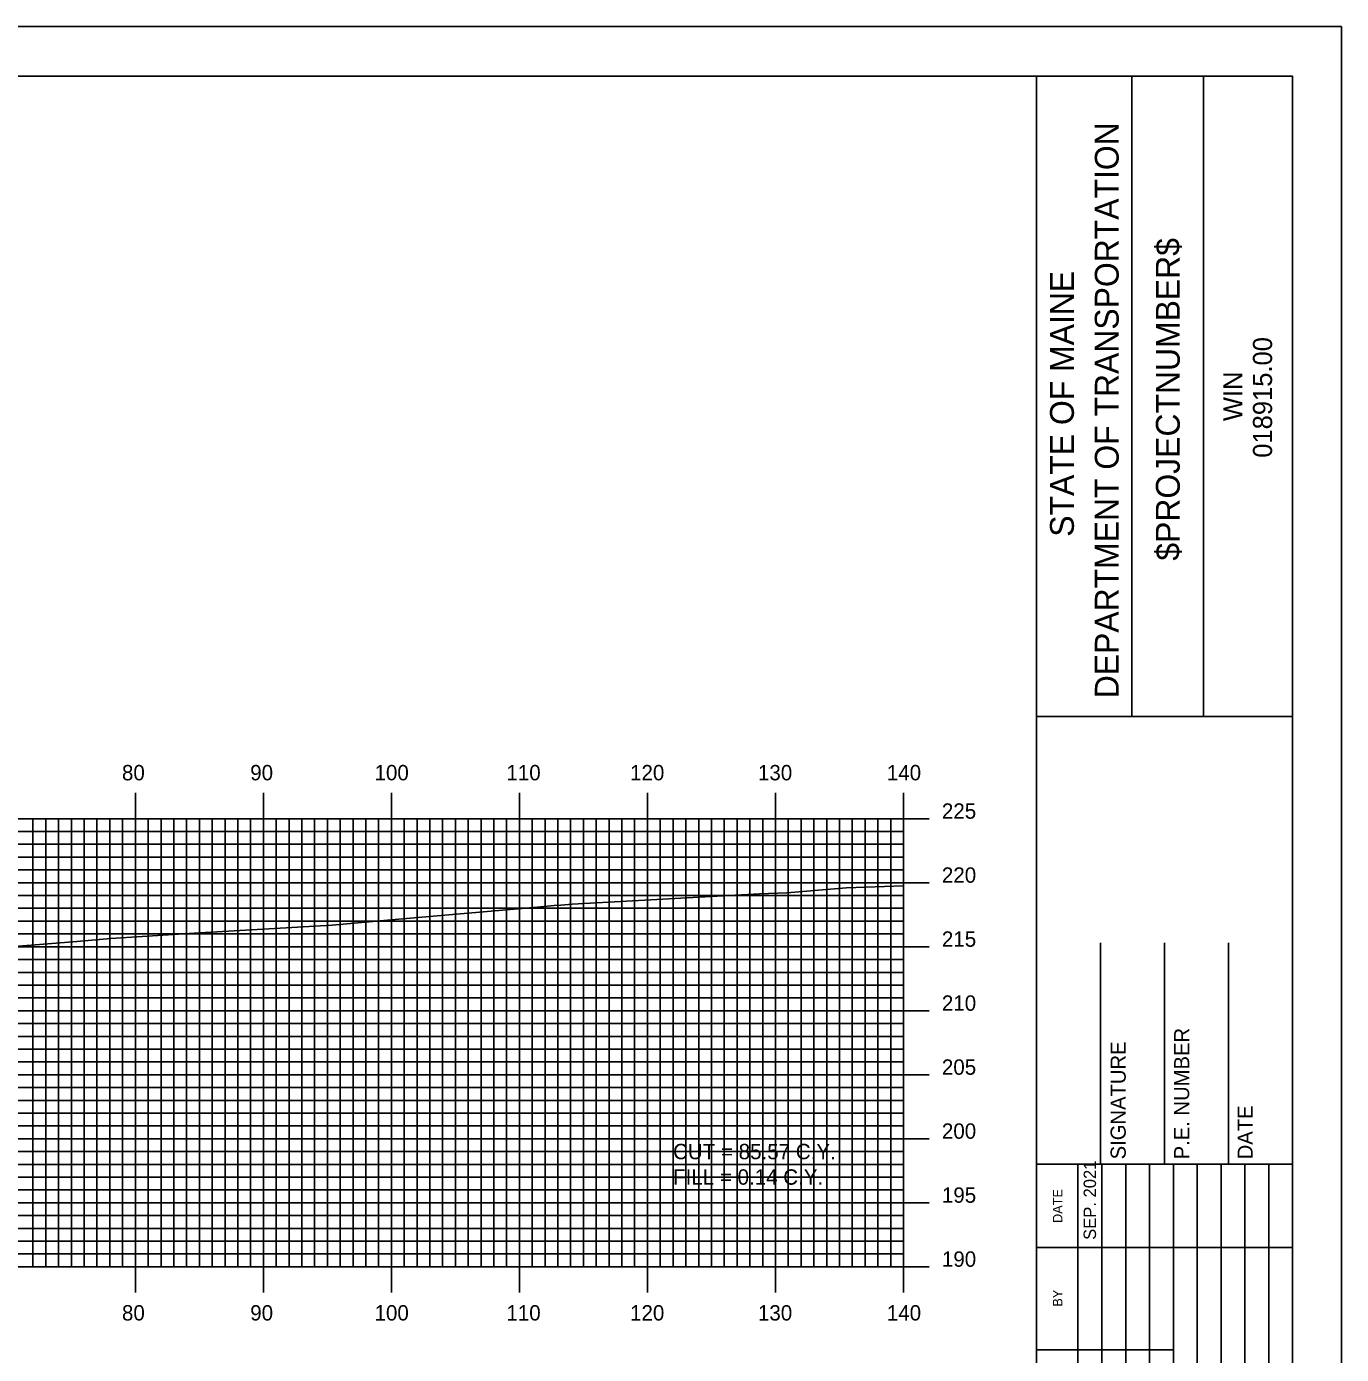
# Model space of a CAD drawing. Extents: x 852135 to 852479, y 364785 to 365005.
# Drawn here: x 852372.7 to 852475.4, y 364901.4 to 365005.1 of the extents above; entities that cross this region are included whole.
import ezdxf

# ---------------------------------------------------------------- set-up
doc = ezdxf.new("R2010")
doc.units = 0
for name, color, linetype in [('BORDER', 7, 'Continuous'), ('D_Text_Standard', 7, 'Continuous'), ('H_V ANNOTATION', 7, 'Continuous'), ('MAJOR', 7, 'Continuous'), ('MINOR', 7, 'Continuous'), ('PLOT BOUNDARY', 7, 'Continuous'), ('S_Roadway_Centerline', 7, 'Continuous')]:
    doc.layers.add(name, color=color, linetype=linetype)

msp = doc.modelspace()

# ---------------------------------------------------------------- linework, layer by layer
at = {"layer": 'BORDER'}
for p, q in [((852451.62, 364791.23), (852451.62, 365001.23)), ((852459.07, 364951.23), (852459.07, 365001.23)), ((852464.66, 364951.23), (852464.66, 365001.23)), ((852451.62, 364951.22), (852471.62, 364951.22)), ((852456.62, 364916.24), (852456.62, 364933.53)), ((852461.62, 364916.24), (852461.62, 364933.53)), ((852466.62, 364916.24), (852466.62, 364933.53)), ((852451.62, 364916.24), (852471.62, 364916.24))]:
    msp.add_line(p, q, dxfattribs=at)
msp.add_lwpolyline([(852151.62, 364791.23), (852471.62, 364791.23), (852471.62, 365001.23), (852151.62, 365001.23)], close=True, dxfattribs=at)
for points in [[(852454.85, 364909.74), (852454.85, 364916.24)], [(852456.71, 364881.24), (852456.71, 364916.24)], [(852458.58, 364916.24), (852458.58, 364881.24)], [(852460.44, 364881.24), (852460.44, 364916.24)], [(852462.3, 364881.24), (852462.3, 364916.24)], [(852464.17, 364881.24), (852464.17, 364916.24)], [(852466.03, 364881.24), (852466.03, 364916.24)], [(852467.89, 364881.24), (852467.89, 364916.24)], [(852469.76, 364881.24), (852469.76, 364916.24)], [(852454.85, 364881.24), (852454.85, 364914.83)], [(852451.62, 364909.74), (852471.62, 364909.74)], [(852451.62, 364901.74), (852454.85, 364901.74)], [(852454.85, 364901.74), (852462.3, 364901.74)]]:
    msp.add_lwpolyline(points, dxfattribs=at)
at = {"layer": 'MAJOR'}
for p, q in [((852381.22, 364945.24), (852381.22, 364943.23)), ((852391.22, 364945.24), (852391.22, 364943.23)), ((852401.22, 364945.24), (852401.22, 364943.23)), ((852411.22, 364945.24), (852411.22, 364943.23)), ((852421.22, 364945.24), (852421.22, 364943.23)), ((852431.22, 364945.24), (852431.22, 364943.23)), ((852441.22, 364945.24), (852441.22, 364943.23)), ((852161.22, 364943.23), (852441.22, 364943.23)), ((852161.22, 364943.23), (852441.22, 364943.23)), ((852381.22, 364908.23), (852381.22, 364943.23)), ((852391.22, 364908.23), (852391.22, 364943.23)), ((852401.22, 364908.23), (852401.22, 364943.23)), ((852411.22, 364908.23), (852411.22, 364943.23)), ((852421.22, 364908.23), (852421.22, 364943.23)), ((852431.22, 364908.23), (852431.22, 364943.23)), ((852443.22, 364943.23), (852439.21, 364943.23)), ((852441.22, 364908.23), (852441.22, 364943.23)), ((852441.22, 364908.23), (852441.22, 364943.23)), ((852161.22, 364938.23), (852441.22, 364938.23)), ((852443.22, 364938.23), (852439.21, 364938.23)), ((852161.22, 364933.23), (852441.22, 364933.23)), ((852443.22, 364933.23), (852439.21, 364933.23)), ((852161.22, 364928.23), (852441.22, 364928.23)), ((852443.22, 364928.23), (852439.21, 364928.23)), ((852161.22, 364923.23), (852441.22, 364923.23)), ((852443.22, 364923.23), (852439.21, 364923.23)), ((852161.22, 364918.23), (852441.22, 364918.23)), ((852443.22, 364918.23), (852439.21, 364918.23)), ((852161.22, 364913.23), (852441.22, 364913.23)), ((852443.22, 364913.23), (852439.21, 364913.23)), ((852161.22, 364908.23), (852441.22, 364908.23)), ((852161.22, 364908.23), (852441.22, 364908.23)), ((852381.22, 364906.23), (852381.22, 364908.23)), ((852391.22, 364906.23), (852391.22, 364908.23)), ((852401.22, 364906.23), (852401.22, 364908.23)), ((852411.22, 364906.23), (852411.22, 364908.23)), ((852421.22, 364906.23), (852421.22, 364908.23)), ((852431.22, 364906.23), (852431.22, 364908.23)), ((852443.22, 364908.23), (852439.21, 364908.23)), ((852441.22, 364906.23), (852441.22, 364908.23))]:
    msp.add_line(p, q, dxfattribs=at)
at = {"layer": 'MINOR'}
for p, q in [((852373.22, 364908.23), (852373.22, 364943.23)), ((852374.22, 364908.23), (852374.22, 364943.23)), ((852375.22, 364908.23), (852375.22, 364943.23)), ((852376.22, 364908.23), (852376.22, 364943.23)), ((852377.22, 364908.23), (852377.22, 364943.23)), ((852378.22, 364908.23), (852378.22, 364943.23)), ((852379.22, 364908.23), (852379.22, 364943.23)), ((852380.22, 364908.23), (852380.22, 364943.23)), ((852382.22, 364908.23), (852382.22, 364943.23)), ((852383.22, 364908.23), (852383.22, 364943.23)), ((852384.22, 364908.23), (852384.22, 364943.23)), ((852385.22, 364908.23), (852385.22, 364943.23)), ((852386.22, 364908.23), (852386.22, 364943.23)), ((852387.22, 364908.23), (852387.22, 364943.23)), ((852388.22, 364908.23), (852388.22, 364943.23)), ((852389.22, 364908.23), (852389.22, 364943.23)), ((852390.22, 364908.23), (852390.22, 364943.23)), ((852392.22, 364908.23), (852392.22, 364943.23)), ((852393.22, 364908.23), (852393.22, 364943.23)), ((852394.22, 364908.23), (852394.22, 364943.23)), ((852395.22, 364908.23), (852395.22, 364943.23)), ((852396.22, 364908.23), (852396.22, 364943.23)), ((852397.22, 364908.23), (852397.22, 364943.23)), ((852398.22, 364908.23), (852398.22, 364943.23)), ((852399.22, 364908.23), (852399.22, 364943.23)), ((852400.22, 364908.23), (852400.22, 364943.23)), ((852402.22, 364908.23), (852402.22, 364943.23)), ((852403.22, 364908.23), (852403.22, 364943.23)), ((852404.22, 364908.23), (852404.22, 364943.23)), ((852405.22, 364908.23), (852405.22, 364943.23)), ((852406.22, 364908.23), (852406.22, 364943.23)), ((852407.22, 364908.23), (852407.22, 364943.23)), ((852408.22, 364908.23), (852408.22, 364943.23)), ((852409.22, 364908.23), (852409.22, 364943.23)), ((852410.22, 364908.23), (852410.22, 364943.23)), ((852412.22, 364908.23), (852412.22, 364943.23)), ((852413.22, 364908.23), (852413.22, 364943.23)), ((852414.22, 364908.23), (852414.22, 364943.23)), ((852415.22, 364908.23), (852415.22, 364943.23)), ((852416.22, 364908.23), (852416.22, 364943.23)), ((852417.22, 364908.23), (852417.22, 364943.23)), ((852418.22, 364908.23), (852418.22, 364943.23)), ((852419.22, 364908.23), (852419.22, 364943.23)), ((852420.22, 364908.23), (852420.22, 364943.23)), ((852422.22, 364908.23), (852422.22, 364943.23)), ((852423.22, 364908.23), (852423.22, 364943.23)), ((852424.22, 364908.23), (852424.22, 364943.23)), ((852425.22, 364908.23), (852425.22, 364943.23)), ((852426.22, 364908.23), (852426.22, 364943.23)), ((852427.22, 364908.23), (852427.22, 364943.23)), ((852428.22, 364908.23), (852428.22, 364943.23)), ((852429.22, 364908.23), (852429.22, 364943.23)), ((852430.22, 364908.23), (852430.22, 364943.23)), ((852432.22, 364908.23), (852432.22, 364943.23)), ((852433.22, 364908.23), (852433.22, 364943.23)), ((852434.22, 364908.23), (852434.22, 364943.23)), ((852435.22, 364908.23), (852435.22, 364943.23)), ((852436.22, 364908.23), (852436.22, 364943.23)), ((852437.22, 364908.23), (852437.22, 364943.23)), ((852438.22, 364908.23), (852438.22, 364943.23)), ((852439.22, 364908.23), (852439.22, 364943.23)), ((852440.22, 364908.23), (852440.22, 364943.23)), ((852161.22, 364942.23), (852441.22, 364942.23)), ((852441.22, 364942.23), (852439.21, 364942.23)), ((852161.22, 364941.23), (852441.22, 364941.23)), ((852441.22, 364941.23), (852439.21, 364941.23)), ((852161.22, 364940.23), (852441.22, 364940.23)), ((852441.22, 364940.23), (852439.21, 364940.23)), ((852161.22, 364939.23), (852441.22, 364939.23)), ((852441.22, 364939.23), (852439.21, 364939.23)), ((852161.22, 364937.23), (852441.22, 364937.23)), ((852441.22, 364937.23), (852439.21, 364937.23)), ((852161.22, 364936.23), (852441.22, 364936.23)), ((852441.22, 364936.23), (852439.21, 364936.23)), ((852161.22, 364935.23), (852441.22, 364935.23)), ((852441.22, 364935.23), (852439.21, 364935.23)), ((852161.22, 364934.23), (852441.22, 364934.23)), ((852441.22, 364934.23), (852439.21, 364934.23)), ((852161.22, 364932.23), (852441.22, 364932.23)), ((852441.22, 364932.23), (852439.21, 364932.23)), ((852161.22, 364931.23), (852441.22, 364931.23)), ((852441.22, 364931.23), (852439.21, 364931.23)), ((852161.22, 364930.23), (852441.22, 364930.23)), ((852441.22, 364930.23), (852439.21, 364930.23)), ((852161.22, 364929.23), (852441.22, 364929.23)), ((852441.22, 364929.23), (852439.21, 364929.23)), ((852161.22, 364927.23), (852441.22, 364927.23)), ((852441.22, 364927.23), (852439.21, 364927.23)), ((852161.22, 364926.23), (852441.22, 364926.23)), ((852441.22, 364926.23), (852439.21, 364926.23)), ((852161.22, 364925.23), (852441.22, 364925.23)), ((852441.22, 364925.23), (852439.21, 364925.23)), ((852161.22, 364924.23), (852441.22, 364924.23)), ((852441.22, 364924.23), (852439.21, 364924.23)), ((852161.22, 364922.23), (852441.22, 364922.23)), ((852441.22, 364922.23), (852439.21, 364922.23)), ((852161.22, 364921.23), (852441.22, 364921.23)), ((852441.22, 364921.23), (852439.21, 364921.23)), ((852161.22, 364920.23), (852441.22, 364920.23)), ((852441.22, 364920.23), (852439.21, 364920.23)), ((852161.22, 364919.23), (852441.22, 364919.23)), ((852441.22, 364919.23), (852439.21, 364919.23)), ((852161.22, 364917.23), (852441.22, 364917.23)), ((852441.22, 364917.23), (852439.21, 364917.23)), ((852161.22, 364916.23), (852441.22, 364916.23)), ((852441.22, 364916.23), (852439.21, 364916.23)), ((852161.22, 364915.23), (852441.22, 364915.23)), ((852441.22, 364915.23), (852439.21, 364915.23)), ((852161.22, 364914.23), (852441.22, 364914.23)), ((852441.22, 364914.23), (852439.21, 364914.23)), ((852161.22, 364912.23), (852441.22, 364912.23)), ((852441.22, 364912.23), (852439.21, 364912.23)), ((852161.22, 364911.23), (852441.22, 364911.23)), ((852441.22, 364911.23), (852439.21, 364911.23)), ((852161.22, 364910.23), (852441.22, 364910.23)), ((852441.22, 364910.23), (852439.21, 364910.23)), ((852161.22, 364909.23), (852441.22, 364909.23)), ((852441.22, 364909.23), (852439.21, 364909.23))]:
    msp.add_line(p, q, dxfattribs=at)
at = {"layer": 'PLOT BOUNDARY'}
msp.add_lwpolyline([(852135.43, 364785.11), (852475.43, 364785.11), (852475.43, 365005.11), (852135.43, 365005.11)], close=True, dxfattribs=at)
at = {"layer": 'S_Roadway_Centerline'}
msp.add_lwpolyline([(852369.15, 364933.04), (852376.64, 364933.64), (852379.29, 364933.87), (852386.22, 364934.32), (852396.58, 364934.92), (852401.19, 364935.34), (852412.61, 364936.32), (852413.93, 364936.45), (852414.44, 364936.49), (852415.33, 364936.55), (852429.97, 364937.36), (852432.1, 364937.45), (852436.78, 364937.82), (852441.22, 364937.99)], dxfattribs=at)

# ---------------------------------------------------------------- texts
at = {"layer": 'BORDER'}
for s, height, p in [('DEPARTMENT OF TRANSPORTATION', 1.8635, (852458.03, 364952.64)), ('$PROJECTNUMBER$', 1.8635, (852462.8, 364963.39)), ('STATE OF MAINE', 1.8635, (852454.53, 364965.26)), ('018915.00', 1.491, (852470.01, 364971.43)), ('WIN', 1.491, (852467.69, 364974.29)), ('P.E. NUMBER', 1.1811, (852463.54, 364916.62)), ('SIGNATURE', 1.181, (852458.58, 364916.62)), ('DATE', 1.181, (852468.5, 364916.62)), ('SEP. 2021', 0.969, (852456.26, 364910.33)), ('DATE', 0.743, (852453.63, 364911.65)), ('BY', 0.743, (852453.63, 364905.11))]:
    msp.add_text(s, height=height, rotation=90, dxfattribs=at).set_placement(p)
at = {"layer": 'D_Text_Standard'}
for s, p in [('CUT = 85.57 C.Y.', (852423.22, 364916.63)), ('FILL = 0.14 C.Y.', (852423.22, 364914.64))]:
    msp.add_text(s, height=1.2, dxfattribs=at).set_placement(p)
at = {"layer": 'H_V ANNOTATION'}
for s, p in [('80', (852380.17, 364946.23)), ('90', (852390.19, 364946.23)), ('100', (852399.9, 364946.23)), ('110', (852410.2, 364946.23)), ('120', (852419.86, 364946.23)), ('130', (852429.85, 364946.23)), ('140', (852439.92, 364946.23)), ('225', (852444.22, 364943.23)), ('220', (852444.22, 364938.23)), ('215', (852444.22, 364933.23)), ('210', (852444.22, 364928.23)), ('205', (852444.22, 364923.23)), ('200', (852444.22, 364918.23)), ('195', (852444.22, 364913.23)), ('190', (852444.22, 364908.23)), ('80', (852380.17, 364904.03)), ('90', (852390.19, 364904.03)), ('100', (852399.9, 364904.03)), ('110', (852410.2, 364904.03)), ('120', (852419.86, 364904.03)), ('130', (852429.85, 364904.03)), ('140', (852439.92, 364904.03))]:
    msp.add_text(s, height=1.2, dxfattribs=at).set_placement(p)

doc.saveas('drawing.dxf')
